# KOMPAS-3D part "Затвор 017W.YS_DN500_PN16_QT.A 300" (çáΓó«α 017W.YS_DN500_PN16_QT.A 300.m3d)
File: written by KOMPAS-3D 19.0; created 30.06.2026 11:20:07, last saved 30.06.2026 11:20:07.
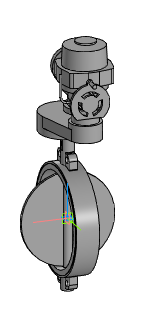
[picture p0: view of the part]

Document properties: Автор: Энергия

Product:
- Part/product: Затвор 017W.YS_DN500_PN16_QT.A 300
    Масса: 335.507

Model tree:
1. Операция без истории:1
